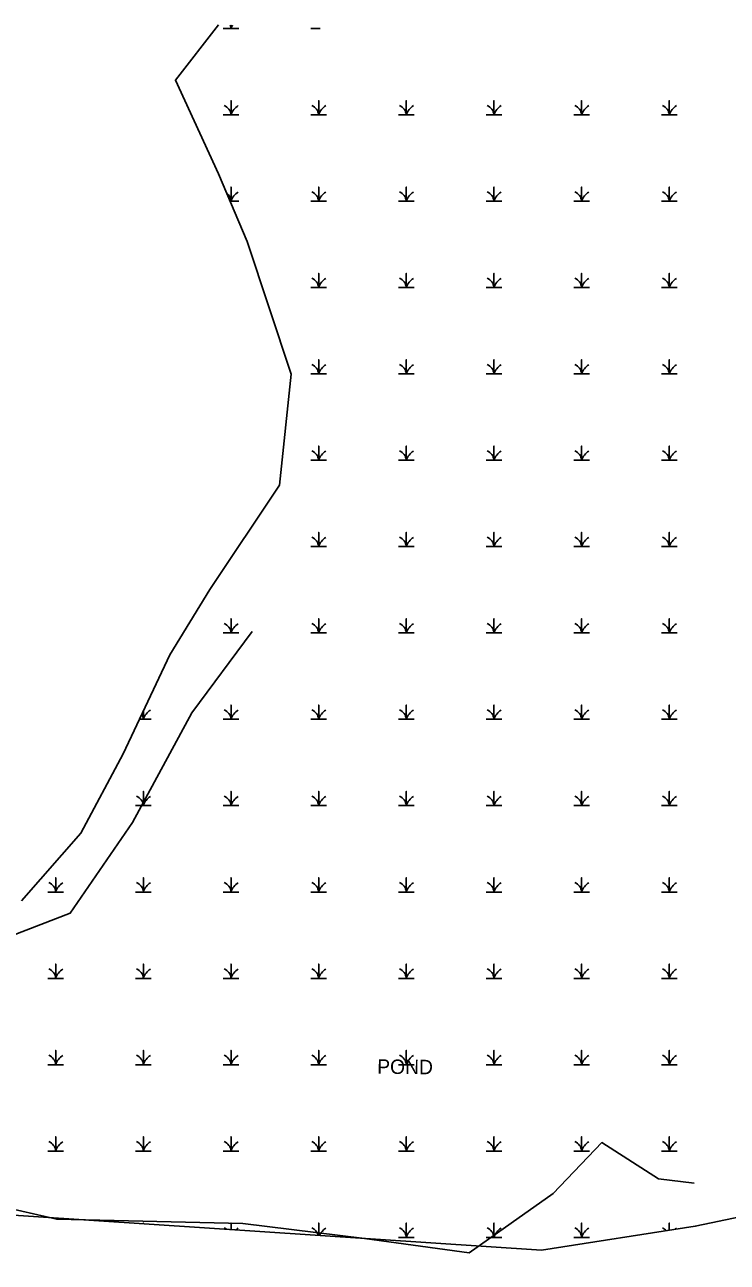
# Model space of a CAD drawing. Extents: x 2169223 to 2172151, y 723262 to 725175.
# Drawn here: x 2171113.8 to 2171308.7, y 724083.8 to 724427 of the extents above; entities that cross this region are included whole.
import ezdxf

# ---------------------------------------------------------------- set-up
doc = ezdxf.new("R2010")
doc.units = 0
for name, color, linetype in [('Default', 7, 'Continuous'), ('Exist Hydro Pool or Reservoir', 7, 'Continuous'), ('Exist Utilities Water UG Line', 7, 'Continuous')]:
    doc.layers.add(name, color=color, linetype=linetype)

msp = doc.modelspace()

# ---------------------------------------------------------------- linework, layer by layer
at = {"layer": 'Default'}
for points in [[(2171112.89, 724183.96), (2171129.39, 724202.76), (2171141.13, 724224.8), (2171154.05, 724252.28), (2171165.12, 724270.38), (2171184.46, 724299.31), (2171187.73, 724330.09), (2171175.54, 724366.84), (2171167.54, 724385.65), (2171155.61, 724411.6), (2171167.57, 724427)], [(2171168.87, 724425.95), (2171168.98, 724425.95)], [(2171168.98, 724425.95), (2171171.03, 724425.95), (2171171.03, 724426.88)], [(2171171.03, 724426.88), (2171171.03, 724425.95), (2171173.18, 724425.95)], [(2171193.19, 724425.95), (2171195.34, 724425.95), (2171195.34, 724425.97)], [(2171195.34, 724425.97), (2171195.34, 724425.95), (2171195.74, 724425.95)], [(2171646.71, 724409.08), (2171639.12, 724404.07), (2171615.95, 724359.66), (2171585.14, 724346.96), (2171572.27, 724330.12), (2171541.38, 724278.6), (2171494.05, 724272.59), (2171450.52, 724247.37), (2171445.92, 724243.67), (2171427.74, 724238.82), (2171406.38, 724186.3), (2171401.13, 724168.54), (2171393.3, 724167.45), (2171368.95, 724149.15), (2171363.45, 724127.38), (2171338.31, 724101.83), (2171299.81, 724093.74), (2171257.11, 724087.08), (2171085.47, 724098.48), (2171084.69, 724158.24), (2171059.94, 724158.08), (2171055.72, 724108.27), (2171040.51, 724083.75)], [(2171168.87, 724402), (2171171.03, 724402), (2171171.03, 724405.95), (2171171.03, 724402), (2171173.18, 724402)], [(2171193.19, 724402), (2171195.34, 724402), (2171195.34, 724405.95), (2171195.34, 724402), (2171197.49, 724402)], [(2171217.5, 724402), (2171219.65, 724402), (2171219.65, 724405.95), (2171219.65, 724402), (2171221.8, 724402)], [(2171241.81, 724402), (2171243.96, 724402), (2171243.96, 724405.95), (2171243.96, 724402), (2171246.11, 724402)], [(2171266.12, 724402), (2171268.28, 724402), (2171268.28, 724405.95), (2171268.28, 724402), (2171270.43, 724402)], [(2171290.44, 724402), (2171292.59, 724402), (2171292.59, 724405.95), (2171292.59, 724402), (2171294.74, 724402)], [(2171170.77, 724378.05), (2171171.03, 724378.05), (2171171.03, 724382), (2171171.03, 724378.05), (2171173.18, 724378.05)], [(2171193.19, 724378.05), (2171195.34, 724378.05), (2171195.34, 724382), (2171195.34, 724378.05), (2171197.49, 724378.05)], [(2171217.5, 724378.05), (2171219.65, 724378.05), (2171219.65, 724382), (2171219.65, 724378.05), (2171221.8, 724378.05)], [(2171241.81, 724378.05), (2171243.96, 724378.05), (2171243.96, 724382), (2171243.96, 724378.05), (2171246.11, 724378.05)], [(2171266.12, 724378.05), (2171268.28, 724378.05), (2171268.28, 724382), (2171268.28, 724378.05), (2171270.43, 724378.05)], [(2171290.44, 724378.05), (2171292.59, 724378.05), (2171292.59, 724382), (2171292.59, 724378.05), (2171294.74, 724378.05)], [(2171193.19, 724354.1), (2171195.34, 724354.1), (2171195.34, 724358.05), (2171195.34, 724354.1), (2171197.49, 724354.1)], [(2171217.5, 724354.1), (2171219.65, 724354.1), (2171219.65, 724358.05), (2171219.65, 724354.1), (2171221.8, 724354.1)], [(2171241.81, 724354.1), (2171243.96, 724354.1), (2171243.96, 724358.05), (2171243.96, 724354.1), (2171246.11, 724354.1)], [(2171266.12, 724354.1), (2171268.28, 724354.1), (2171268.28, 724358.05), (2171268.28, 724354.1), (2171270.43, 724354.1)], [(2171290.44, 724354.1), (2171292.59, 724354.1), (2171292.59, 724358.05), (2171292.59, 724354.1), (2171294.74, 724354.1)], [(2171193.19, 724330.15), (2171195.34, 724330.15), (2171195.34, 724334.1), (2171195.34, 724330.15), (2171197.49, 724330.15)], [(2171217.5, 724330.15), (2171219.65, 724330.15), (2171219.65, 724334.1), (2171219.65, 724330.15), (2171221.8, 724330.15)], [(2171241.81, 724330.15), (2171243.96, 724330.15), (2171243.96, 724334.1), (2171243.96, 724330.15), (2171246.11, 724330.15)], [(2171266.12, 724330.15), (2171268.28, 724330.15), (2171268.28, 724334.1), (2171268.28, 724330.15), (2171270.43, 724330.15)], [(2171290.44, 724330.15), (2171292.59, 724330.15), (2171292.59, 724334.1), (2171292.59, 724330.15), (2171294.74, 724330.15)], [(2171193.19, 724306.2), (2171195.34, 724306.2), (2171195.34, 724310.15), (2171195.34, 724306.2), (2171197.49, 724306.2)], [(2171217.5, 724306.2), (2171219.65, 724306.2), (2171219.65, 724310.15), (2171219.65, 724306.2), (2171221.8, 724306.2)], [(2171241.81, 724306.2), (2171243.96, 724306.2), (2171243.96, 724310.15), (2171243.96, 724306.2), (2171246.11, 724306.2)], [(2171266.12, 724306.2), (2171268.28, 724306.2), (2171268.28, 724310.15), (2171268.28, 724306.2), (2171270.43, 724306.2)], [(2171290.44, 724306.2), (2171292.59, 724306.2), (2171292.59, 724310.15), (2171292.59, 724306.2), (2171294.74, 724306.2)], [(2171193.19, 724282.25), (2171195.34, 724282.25), (2171195.34, 724286.2), (2171195.34, 724282.25), (2171197.49, 724282.25)], [(2171217.5, 724282.25), (2171219.65, 724282.25), (2171219.65, 724286.2), (2171219.65, 724282.25), (2171221.8, 724282.25)], [(2171241.81, 724282.25), (2171243.96, 724282.25), (2171243.96, 724286.2), (2171243.96, 724282.25), (2171246.11, 724282.25)], [(2171266.12, 724282.25), (2171268.28, 724282.25), (2171268.28, 724286.2), (2171268.28, 724282.25), (2171270.43, 724282.25)], [(2171290.44, 724282.25), (2171292.59, 724282.25), (2171292.59, 724286.2), (2171292.59, 724282.25), (2171294.74, 724282.25)], [(2171173.06, 724282.25), (2171173.18, 724282.25)], [(2171168.87, 724258.3), (2171171.03, 724258.3), (2171171.03, 724262.25), (2171171.03, 724258.3), (2171173.18, 724258.3)], [(2171193.19, 724258.3), (2171195.34, 724258.3), (2171195.34, 724262.25), (2171195.34, 724258.3), (2171197.49, 724258.3)], [(2171217.5, 724258.3), (2171219.65, 724258.3), (2171219.65, 724262.25), (2171219.65, 724258.3), (2171221.8, 724258.3)], [(2171241.81, 724258.3), (2171243.96, 724258.3), (2171243.96, 724262.25), (2171243.96, 724258.3), (2171246.11, 724258.3)], [(2171266.12, 724258.3), (2171268.28, 724258.3), (2171268.28, 724262.25), (2171268.28, 724258.3), (2171270.43, 724258.3)], [(2171290.44, 724258.3), (2171292.59, 724258.3), (2171292.59, 724262.25), (2171292.59, 724258.3), (2171294.74, 724258.3)], [(2171145.62, 724234.35), (2171146.71, 724234.35), (2171146.71, 724236.67)], [(2171146.71, 724236.67), (2171146.71, 724234.35), (2171148.86, 724234.35)], [(2171168.87, 724234.35), (2171171.03, 724234.35), (2171171.03, 724238.3), (2171171.03, 724234.35), (2171173.18, 724234.35)], [(2171193.19, 724234.35), (2171195.34, 724234.35), (2171195.34, 724238.3), (2171195.34, 724234.35), (2171197.49, 724234.35)], [(2171217.5, 724234.35), (2171219.65, 724234.35), (2171219.65, 724238.3), (2171219.65, 724234.35), (2171221.8, 724234.35)], [(2171241.81, 724234.35), (2171243.96, 724234.35), (2171243.96, 724238.3), (2171243.96, 724234.35), (2171246.11, 724234.35)], [(2171266.12, 724234.35), (2171268.28, 724234.35), (2171268.28, 724238.3), (2171268.28, 724234.35), (2171270.43, 724234.35)], [(2171290.44, 724234.35), (2171292.59, 724234.35), (2171292.59, 724238.3), (2171292.59, 724234.35), (2171294.74, 724234.35)], [(2171144.56, 724210.4), (2171146.71, 724210.4), (2171146.71, 724214.35), (2171146.71, 724210.4), (2171148.86, 724210.4)], [(2171168.87, 724210.4), (2171171.03, 724210.4), (2171171.03, 724214.35), (2171171.03, 724210.4), (2171173.18, 724210.4)], [(2171193.19, 724210.4), (2171195.34, 724210.4), (2171195.34, 724214.35), (2171195.34, 724210.4), (2171197.49, 724210.4)], [(2171217.5, 724210.4), (2171219.65, 724210.4), (2171219.65, 724214.35), (2171219.65, 724210.4), (2171221.8, 724210.4)], [(2171241.81, 724210.4), (2171243.96, 724210.4), (2171243.96, 724214.35), (2171243.96, 724210.4), (2171246.11, 724210.4)], [(2171266.12, 724210.4), (2171268.28, 724210.4), (2171268.28, 724214.35), (2171268.28, 724210.4), (2171270.43, 724210.4)], [(2171290.44, 724210.4), (2171292.59, 724210.4), (2171292.59, 724214.35), (2171292.59, 724210.4), (2171294.74, 724210.4)], [(2171120.25, 724186.45), (2171122.4, 724186.45), (2171122.4, 724190.4), (2171122.4, 724186.45), (2171124.55, 724186.45)], [(2171144.56, 724186.45), (2171146.71, 724186.45), (2171146.71, 724190.4), (2171146.71, 724186.45), (2171148.86, 724186.45)], [(2171168.87, 724186.45), (2171171.03, 724186.45), (2171171.03, 724190.4), (2171171.03, 724186.45), (2171173.18, 724186.45)], [(2171193.19, 724186.45), (2171195.34, 724186.45), (2171195.34, 724190.4), (2171195.34, 724186.45), (2171197.49, 724186.45)], [(2171217.5, 724186.45), (2171219.65, 724186.45), (2171219.65, 724190.4), (2171219.65, 724186.45), (2171221.8, 724186.45)], [(2171241.81, 724186.45), (2171243.96, 724186.45), (2171243.96, 724190.4), (2171243.96, 724186.45), (2171246.11, 724186.45)], [(2171266.12, 724186.45), (2171268.28, 724186.45), (2171268.28, 724190.4), (2171268.28, 724186.45), (2171270.43, 724186.45)], [(2171290.44, 724186.45), (2171292.59, 724186.45), (2171292.59, 724190.4), (2171292.59, 724186.45), (2171294.74, 724186.45)], [(2171120.25, 724162.5), (2171122.4, 724162.5), (2171122.4, 724166.45), (2171122.4, 724162.5), (2171124.55, 724162.5)], [(2171144.56, 724162.5), (2171146.71, 724162.5), (2171146.71, 724166.45), (2171146.71, 724162.5), (2171148.86, 724162.5)], [(2171168.87, 724162.5), (2171171.03, 724162.5), (2171171.03, 724166.45), (2171171.03, 724162.5), (2171173.18, 724162.5)], [(2171193.19, 724162.5), (2171195.34, 724162.5), (2171195.34, 724166.45), (2171195.34, 724162.5), (2171197.49, 724162.5)], [(2171217.5, 724162.5), (2171219.65, 724162.5), (2171219.65, 724166.45), (2171219.65, 724162.5), (2171221.8, 724162.5)], [(2171241.81, 724162.5), (2171243.96, 724162.5), (2171243.96, 724166.45), (2171243.96, 724162.5), (2171246.11, 724162.5)], [(2171266.12, 724162.5), (2171268.28, 724162.5), (2171268.28, 724166.45), (2171268.28, 724162.5), (2171270.43, 724162.5)], [(2171290.44, 724162.5), (2171292.59, 724162.5), (2171292.59, 724166.45), (2171292.59, 724162.5), (2171294.74, 724162.5)], [(2171120.25, 724138.55), (2171122.4, 724138.55), (2171122.4, 724142.5), (2171122.4, 724138.55), (2171124.55, 724138.55)], [(2171144.56, 724138.55), (2171146.71, 724138.55), (2171146.71, 724142.5), (2171146.71, 724138.55), (2171148.86, 724138.55)], [(2171168.87, 724138.55), (2171171.03, 724138.55), (2171171.03, 724142.5), (2171171.03, 724138.55), (2171173.18, 724138.55)], [(2171193.19, 724138.55), (2171195.34, 724138.55), (2171195.34, 724142.5), (2171195.34, 724138.55), (2171197.49, 724138.55)], [(2171217.5, 724138.55), (2171219.65, 724138.55), (2171219.65, 724142.5), (2171219.65, 724138.55), (2171221.8, 724138.55)], [(2171241.81, 724138.55), (2171243.96, 724138.55), (2171243.96, 724142.5), (2171243.96, 724138.55), (2171246.11, 724138.55)], [(2171266.12, 724138.55), (2171268.28, 724138.55), (2171268.28, 724142.5), (2171268.28, 724138.55), (2171270.43, 724138.55)], [(2171290.44, 724138.55), (2171292.59, 724138.55), (2171292.59, 724142.5), (2171292.59, 724138.55), (2171294.74, 724138.55)], [(2171120.25, 724114.6), (2171122.4, 724114.6), (2171122.4, 724118.55), (2171122.4, 724114.6), (2171124.55, 724114.6)], [(2171144.56, 724114.6), (2171146.71, 724114.6), (2171146.71, 724118.55), (2171146.71, 724114.6), (2171148.86, 724114.6)], [(2171168.87, 724114.6), (2171171.03, 724114.6), (2171171.03, 724118.55), (2171171.03, 724114.6), (2171173.18, 724114.6)], [(2171193.19, 724114.6), (2171195.34, 724114.6), (2171195.34, 724118.55), (2171195.34, 724114.6), (2171197.49, 724114.6)], [(2171217.5, 724114.6), (2171219.65, 724114.6), (2171219.65, 724118.55), (2171219.65, 724114.6), (2171221.8, 724114.6)], [(2171241.81, 724114.6), (2171243.96, 724114.6), (2171243.96, 724118.55), (2171243.96, 724114.6), (2171246.11, 724114.6)], [(2171266.12, 724114.6), (2171268.28, 724114.6), (2171268.28, 724118.55), (2171268.28, 724114.6), (2171270.43, 724114.6)], [(2171290.44, 724114.6), (2171292.59, 724114.6), (2171292.59, 724118.55), (2171292.59, 724114.6), (2171294.74, 724114.6)], [(2171146.71, 724094.41), (2171146.71, 724094.6), (2171146.71, 724094.41)], [(2171171.03, 724092.8), (2171171.03, 724094.6), (2171171.03, 724092.8)], [(2171195.34, 724091.18), (2171195.34, 724094.6), (2171195.34, 724091.18)], [(2171217.5, 724090.65), (2171219.65, 724090.65), (2171219.65, 724094.6), (2171219.65, 724090.65), (2171221.8, 724090.65)], [(2171241.81, 724090.65), (2171243.96, 724090.65), (2171243.96, 724094.6), (2171243.96, 724090.65), (2171246.11, 724090.65)], [(2171266.12, 724090.65), (2171268.28, 724090.65), (2171268.28, 724094.6), (2171268.28, 724090.65), (2171270.43, 724090.65)], [(2171292.59, 724092.62), (2171292.59, 724094.6), (2171292.59, 724092.62)]]:
    msp.add_lwpolyline(points, dxfattribs=at)
for centre, radius, start, end in [((2171167.96, 724425.73), 3.07, 4.1403, 22.0637), ((2171175.59, 724424.44), 4.81, 149.7003, 161.6222), ((2171199.9, 724424.44), 4.81, 161.4332, 161.6222), ((2171192.27, 724425.73), 3.07, 4.1403, 4.4257), ((2171167.96, 724401.78), 3.07, 4.1403, 67.535), ((2171175.59, 724400.49), 4.81, 122.1274, 161.6222), ((2171192.27, 724401.78), 3.07, 4.1403, 67.535), ((2171199.9, 724400.49), 4.81, 122.1274, 161.6222), ((2171216.58, 724401.78), 3.07, 4.1403, 67.535), ((2171224.21, 724400.49), 4.81, 122.1274, 161.6222), ((2171240.9, 724401.78), 3.07, 4.1403, 67.535), ((2171248.52, 724400.49), 4.81, 122.1274, 161.6222), ((2171265.21, 724401.78), 3.07, 4.1403, 67.535), ((2171272.84, 724400.49), 4.81, 122.1274, 161.6222), ((2171289.52, 724401.78), 3.07, 4.1403, 67.535), ((2171297.15, 724400.49), 4.81, 122.1274, 161.6222), ((2171167.96, 724377.83), 3.07, 4.1403, 52.6425), ((2171175.59, 724376.54), 4.81, 122.1274, 161.6222), ((2171192.27, 724377.83), 3.07, 4.1403, 67.535), ((2171199.9, 724376.54), 4.81, 122.1274, 161.6222), ((2171216.58, 724377.83), 3.07, 4.1403, 67.535), ((2171224.21, 724376.54), 4.81, 122.1274, 161.6222), ((2171240.9, 724377.83), 3.07, 4.1403, 67.535), ((2171248.52, 724376.54), 4.81, 122.1274, 161.6222), ((2171265.21, 724377.83), 3.07, 4.1403, 67.535), ((2171272.84, 724376.54), 4.81, 122.1274, 161.6222), ((2171289.52, 724377.83), 3.07, 4.1403, 67.535), ((2171297.15, 724376.54), 4.81, 122.1274, 161.6222), ((2171192.27, 724353.88), 3.07, 4.1403, 67.535), ((2171199.9, 724352.59), 4.81, 122.1274, 161.6222), ((2171216.58, 724353.88), 3.07, 4.1403, 67.535), ((2171224.21, 724352.59), 4.81, 122.1274, 161.6222), ((2171240.9, 724353.88), 3.07, 4.1403, 67.535), ((2171248.52, 724352.59), 4.81, 122.1274, 161.6222), ((2171265.21, 724353.88), 3.07, 4.1403, 67.535), ((2171272.84, 724352.59), 4.81, 122.1274, 161.6222), ((2171289.52, 724353.88), 3.07, 4.1403, 67.535), ((2171297.15, 724352.59), 4.81, 122.1274, 161.6222), ((2171192.27, 724329.93), 3.07, 4.1403, 67.535), ((2171199.9, 724328.64), 4.81, 122.1274, 161.6222), ((2171216.58, 724329.93), 3.07, 4.1403, 67.535), ((2171224.21, 724328.64), 4.81, 122.1274, 161.6222), ((2171240.9, 724329.93), 3.07, 4.1403, 67.535), ((2171248.52, 724328.64), 4.81, 122.1274, 161.6222), ((2171265.21, 724329.93), 3.07, 4.1403, 67.535), ((2171272.84, 724328.64), 4.81, 122.1274, 161.6222), ((2171289.52, 724329.93), 3.07, 4.1403, 67.535), ((2171297.15, 724328.64), 4.81, 122.1274, 161.6222), ((2171192.27, 724305.98), 3.07, 4.1403, 67.535), ((2171199.9, 724304.69), 4.81, 122.1274, 161.6222), ((2171216.58, 724305.98), 3.07, 4.1403, 67.535), ((2171224.21, 724304.69), 4.81, 122.1274, 161.6222), ((2171240.9, 724305.98), 3.07, 4.1403, 67.535), ((2171248.52, 724304.69), 4.81, 122.1274, 161.6222), ((2171265.21, 724305.98), 3.07, 4.1403, 67.535), ((2171272.84, 724304.69), 4.81, 122.1274, 161.6222), ((2171289.52, 724305.98), 3.07, 4.1403, 67.535), ((2171297.15, 724304.69), 4.81, 122.1274, 161.6222), ((2171192.27, 724282.03), 3.07, 4.1403, 67.535), ((2171199.9, 724280.74), 4.81, 122.1274, 161.6222), ((2171216.58, 724282.03), 3.07, 4.1403, 67.535), ((2171224.21, 724280.74), 4.81, 122.1274, 161.6222), ((2171240.9, 724282.03), 3.07, 4.1403, 67.535), ((2171248.52, 724280.74), 4.81, 122.1274, 161.6222), ((2171265.21, 724282.03), 3.07, 4.1403, 67.535), ((2171272.84, 724280.74), 4.81, 122.1274, 161.6222), ((2171289.52, 724282.03), 3.07, 4.1403, 67.535), ((2171297.15, 724280.74), 4.81, 122.1274, 161.6222), ((2171167.96, 724258.08), 3.07, 4.1403, 67.535), ((2171175.59, 724256.79), 4.81, 122.1274, 161.6222), ((2171192.27, 724258.08), 3.07, 4.1403, 67.535), ((2171199.9, 724256.79), 4.81, 122.1274, 161.6222), ((2171216.58, 724258.08), 3.07, 4.1403, 67.535), ((2171224.21, 724256.79), 4.81, 122.1274, 161.6222), ((2171240.9, 724258.08), 3.07, 4.1403, 67.535), ((2171248.52, 724256.79), 4.81, 122.1274, 161.6222), ((2171265.21, 724258.08), 3.07, 4.1403, 67.535), ((2171272.84, 724256.79), 4.81, 122.1274, 161.6222), ((2171289.52, 724258.08), 3.07, 4.1403, 67.535), ((2171297.15, 724256.79), 4.81, 122.1274, 161.6222), ((2171151.27, 724232.84), 4.81, 122.1274, 161.6222), ((2171167.96, 724234.13), 3.07, 4.1403, 67.535), ((2171175.59, 724232.84), 4.81, 122.1274, 161.6222), ((2171192.27, 724234.13), 3.07, 4.1403, 67.535), ((2171199.9, 724232.84), 4.81, 122.1274, 161.6222), ((2171216.58, 724234.13), 3.07, 4.1403, 67.535), ((2171224.21, 724232.84), 4.81, 122.1274, 161.6222), ((2171240.9, 724234.13), 3.07, 4.1403, 67.535), ((2171248.52, 724232.84), 4.81, 122.1274, 161.6222), ((2171265.21, 724234.13), 3.07, 4.1403, 67.535), ((2171272.84, 724232.84), 4.81, 122.1274, 161.6222), ((2171289.52, 724234.13), 3.07, 4.1403, 67.535), ((2171297.15, 724232.84), 4.81, 122.1274, 161.6222), ((2171143.65, 724234.13), 3.07, 4.1403, 31.3828), ((2171143.65, 724210.18), 3.07, 4.1403, 67.535), ((2171151.27, 724208.89), 4.81, 122.1274, 161.6222), ((2171167.96, 724210.18), 3.07, 4.1403, 67.535), ((2171175.59, 724208.89), 4.81, 122.1274, 161.6222), ((2171192.27, 724210.18), 3.07, 4.1403, 67.535), ((2171199.9, 724208.89), 4.81, 122.1274, 161.6222), ((2171216.58, 724210.18), 3.07, 4.1403, 67.535), ((2171224.21, 724208.89), 4.81, 122.1274, 161.6222), ((2171240.9, 724210.18), 3.07, 4.1403, 67.535), ((2171248.52, 724208.89), 4.81, 122.1274, 161.6222), ((2171265.21, 724210.18), 3.07, 4.1403, 67.535), ((2171272.84, 724208.89), 4.81, 122.1274, 161.6222), ((2171289.52, 724210.18), 3.07, 4.1403, 67.535), ((2171297.15, 724208.89), 4.81, 122.1274, 161.6222), ((2171119.33, 724186.23), 3.07, 4.1403, 67.535), ((2171126.96, 724184.94), 4.81, 122.1274, 161.6222), ((2171143.65, 724186.23), 3.07, 4.1403, 67.535), ((2171151.27, 724184.94), 4.81, 122.1274, 161.6222), ((2171167.96, 724186.23), 3.07, 4.1403, 67.535), ((2171175.59, 724184.94), 4.81, 122.1274, 161.6222), ((2171192.27, 724186.23), 3.07, 4.1403, 67.535), ((2171199.9, 724184.94), 4.81, 122.1274, 161.6222), ((2171216.58, 724186.23), 3.07, 4.1403, 67.535), ((2171224.21, 724184.94), 4.81, 122.1274, 161.6222), ((2171240.9, 724186.23), 3.07, 4.1403, 67.535), ((2171248.52, 724184.94), 4.81, 122.1274, 161.6222), ((2171265.21, 724186.23), 3.07, 4.1403, 67.535), ((2171272.84, 724184.94), 4.81, 122.1274, 161.6222), ((2171289.52, 724186.23), 3.07, 4.1403, 67.535), ((2171297.15, 724184.94), 4.81, 122.1274, 161.6222), ((2171119.33, 724162.28), 3.07, 4.1403, 67.535), ((2171126.96, 724160.99), 4.81, 122.1274, 161.6222), ((2171143.65, 724162.28), 3.07, 4.1403, 67.535), ((2171151.27, 724160.99), 4.81, 122.1274, 161.6222), ((2171167.96, 724162.28), 3.07, 4.1403, 67.535), ((2171175.59, 724160.99), 4.81, 122.1274, 161.6222), ((2171192.27, 724162.28), 3.07, 4.1403, 67.535), ((2171199.9, 724160.99), 4.81, 122.1274, 161.6222), ((2171216.58, 724162.28), 3.07, 4.1403, 67.535), ((2171224.21, 724160.99), 4.81, 122.1274, 161.6222), ((2171240.9, 724162.28), 3.07, 4.1403, 67.535), ((2171248.52, 724160.99), 4.81, 122.1274, 161.6222), ((2171265.21, 724162.28), 3.07, 4.1403, 67.535), ((2171272.84, 724160.99), 4.81, 122.1274, 161.6222), ((2171289.52, 724162.28), 3.07, 4.1403, 67.535), ((2171297.15, 724160.99), 4.81, 122.1274, 161.6222), ((2171119.33, 724138.33), 3.07, 4.1403, 67.535), ((2171126.96, 724137.04), 4.81, 122.1274, 161.6222), ((2171143.65, 724138.33), 3.07, 4.1403, 67.535), ((2171151.27, 724137.04), 4.81, 122.1274, 161.6222), ((2171167.96, 724138.33), 3.07, 4.1403, 67.535), ((2171175.59, 724137.04), 4.81, 122.1274, 161.6222), ((2171192.27, 724138.33), 3.07, 4.1403, 67.535), ((2171199.9, 724137.04), 4.81, 122.1274, 161.6222), ((2171216.58, 724138.33), 3.07, 4.1403, 67.535), ((2171224.21, 724137.04), 4.81, 122.1274, 161.6222), ((2171240.9, 724138.33), 3.07, 4.1403, 67.535), ((2171248.52, 724137.04), 4.81, 122.1274, 161.6222), ((2171265.21, 724138.33), 3.07, 4.1403, 67.535), ((2171272.84, 724137.04), 4.81, 122.1274, 161.6222), ((2171289.52, 724138.33), 3.07, 4.1403, 67.535), ((2171297.15, 724137.04), 4.81, 122.1274, 161.6222), ((2171119.33, 724114.38), 3.07, 4.1403, 67.535), ((2171126.96, 724113.09), 4.81, 122.1274, 161.6222), ((2171143.65, 724114.38), 3.07, 4.1403, 67.535), ((2171151.27, 724113.09), 4.81, 122.1274, 161.6222), ((2171167.96, 724114.38), 3.07, 4.1403, 67.535), ((2171175.59, 724113.09), 4.81, 122.1274, 161.6222), ((2171192.27, 724114.38), 3.07, 4.1403, 67.535), ((2171199.9, 724113.09), 4.81, 122.1274, 161.6222), ((2171216.58, 724114.38), 3.07, 4.1403, 67.535), ((2171224.21, 724113.09), 4.81, 122.1274, 161.6222), ((2171240.9, 724114.38), 3.07, 4.1403, 67.535), ((2171248.52, 724113.09), 4.81, 122.1274, 161.6222), ((2171265.21, 724114.38), 3.07, 4.1403, 67.535), ((2171272.84, 724113.09), 4.81, 122.1274, 161.6222), ((2171289.52, 724114.38), 3.07, 4.1403, 67.535), ((2171297.15, 724113.09), 4.81, 122.1274, 161.6222), ((2171167.96, 724090.43), 3.07, 52.8069, 67.535), ((2171175.59, 724089.14), 4.81, 122.1274, 131.9742), ((2171192.27, 724090.43), 3.07, 14.3173, 67.535), ((2171199.9, 724089.14), 4.81, 122.1274, 154.9607), ((2171216.58, 724090.43), 3.07, 4.1403, 67.535), ((2171224.21, 724089.14), 4.81, 122.1274, 161.6222), ((2171240.9, 724090.43), 3.07, 4.1403, 67.535), ((2171248.52, 724089.14), 4.81, 122.1274, 161.6222), ((2171265.21, 724090.43), 3.07, 4.1403, 67.535), ((2171272.84, 724089.14), 4.81, 122.1274, 161.6222), ((2171289.52, 724090.43), 3.07, 42.1954, 67.535), ((2171297.15, 724089.14), 4.81, 122.1274, 129.3185)]:
    msp.add_arc(centre, radius, start, end, dxfattribs=at)
at = {"layer": 'Exist Hydro Pool or Reservoir'}
msp.add_lwpolyline([(2171176.9, 724258.74), (2171160.18, 724236.17), (2171143.74, 724205.7), (2171126.42, 724180.58), (2171101.94, 724171.18), (2171094.33, 724149.7), (2171094.48, 724129.88), (2171097.83, 724103.15), (2171106.41, 724099.4), (2171122.68, 724095.66), (2171174.27, 724094.52), (2171208.02, 724090.36), (2171237.1, 724086.39), (2171260.39, 724102.8), (2171273.88, 724116.96), (2171289.64, 724106.85), (2171299.45, 724105.65)], dxfattribs=at)

# ---------------------------------------------------------------- texts
at = {"layer": 'Exist Utilities Water UG Line'}
msp.add_text('POND', height=4, rotation=359.4369, dxfattribs=at).set_placement((2171211.56, 724136.04))

doc.saveas('drawing.dxf')
